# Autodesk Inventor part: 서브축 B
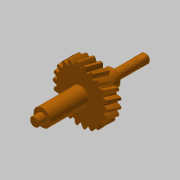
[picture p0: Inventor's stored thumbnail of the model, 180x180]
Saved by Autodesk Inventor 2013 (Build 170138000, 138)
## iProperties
Created: 2020-03
Part Number: 서브축 B
Material: 강철, 탄소
Document SubType Name: Modeling
Designer: mduedu
Categories: <?xml version="1.0" encoding="UTF-16"?> <MemberInstance><Categories><FamilyTemplate><FamilyTemplateParameter ValueType="xs:double" Id="1" ObjectReferenceKey="da
Density: 1 g/cm^3
CustomPartVersion: 1
Author: mduedu
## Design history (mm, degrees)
sketch "Sketch1"
  geometry: C1 r 24.376 at (0, 0)
  constraints: 1 centre point
  dimensions: "d0" = 48.75215 diameter of C1 (= da_da)
extrude "Extrusion1" new body sketch "Sketch1" distance "d1" = 12 (= da_b); taper "d2" = 0 deg
workplane "Work Plane2"
sketch "Sketch2"
  geometry: C1 r 24.376 at (0, 0) reference; C2 r 22.776 at (0, 0)
  constraints: 1 centre point, 1 coincident
  dimensions: "d3" = 45.55215 diameter of C2 (= da_dw)
feature "피치 지름" sketch "Sketch2" dims "d4" = 10, "d5" = 0
workplane "Work Plane8"
workplane "Work Plane9"
feature "스퍼 기어" dims "da_b" = 12, "da_d" = 45.55215, "da_aw" = 45.55215, "da_da" = 48.75215, "da_df" = 41.72415, "da_dw" = 45.55215, angle "da_beta" = 15 deg, "da_lefttooth" = 0, "da_righttooth" = 10
sketch "스케치3"
  geometry: C1 r 7.5 at (0, 0); 1 further point
  constraints: 1 centre point, 1 coincident
  dimensions: "d49" = 15 diameter of C1
extrude "돌출2" join sketch "스케치3" distance "d50" = 34; taper "d51" = 0 deg
sketch "스케치4"
  geometry: C1 r 4 at (0, 0); 1 further point
  constraints: 1 centre point, 1 coincident
  dimensions: "d52" = 8 diameter of C1
extrude "돌출3" join sketch "스케치4" distance "d53" = 7; taper "d54" = 0 deg
sketch "스케치5"
  geometry: C1 r 7.5 at (0, 0); 1 further point
  constraints: 1 centre point, 1 coincident
  dimensions: "d55" = 15 diameter of C1
extrude "돌출4" join sketch "스케치5" distance "d56" = 16; taper "d57" = 0 deg
sketch "스케치6"
  geometry: C1 r 4 at (0, 0); 1 further point
  constraints: 1 centre point, 1 coincident
  dimensions: "d58" = 8 diameter of C1
extrude "돌출5" join sketch "스케치6" distance "d59" = 30; taper "d60" = 0 deg
chamfer "모따기1" distance "d61" = 0.5; stored, may be unused: second distance "d62" = 2, angle "d63" = 45 deg
fillet "모깎기1" dims "d64" = 0.5
sketch "스케치7"
  geometry: L1 (-3.25, -3.25)-(3.25, -3.25); L2 (3.25, -3.25)-(3.25, 3.25); L3 (3.25, 3.25)-(-3.25, 3.25); L4 (-3.25, 3.25)-(-3.25, -3.25); L5 (-3.25, -3.25)-(3.25, 3.25); L6 (3.25, -3.25)-(-3.25, 3.25); L7 (-5, -5)-(5, -5); L8 (5, -5)-(5, 5); L9 (5, 5)-(-5, 5); L10 (-5, 5)-(-5, -5); L11 (-5, -5)-(5, 5); L12 (5, -5)-(-5, 5); 1 further point
  constraints: 24 end point, 4 midpoint, 4 parallel, 2 horizontal, 2 perpendicular
  dimensions: "d65" = 6.5 distance of L3.end L2.end; "d66" = 6.5 distance of L2.end L1.end; "d67" = 10 distance of L9.end L8.end; "d68" = 10 distance of L8.end L7.end
extrude "돌출6" cut sketch "스케치7" distance "d69" = 8; taper "d70" = 0 deg
body "Solid1"
body "Srf1"
other parameters: "d16" = 45.55215 (= da_aw), "d17" = 0, "d34" = 1.428 (computed from da_z), "d39" = 0, "d41" = 0, "d43" = 45.55215 (= da_aw), "d46" = 45.55215 (= da_aw), "d47" = 0, "d48" = 0
